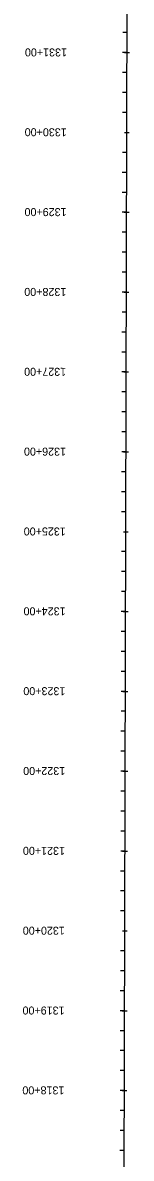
# Model space of a CAD drawing. Extents: x 14541681 to 14544384, y 8572153 to 8583558.
# Drawn here: x 14544128 to 14544264, y 8573573 to 8574996 of the extents above; entities that cross this region are included whole.
import ezdxf

# ---------------------------------------------------------------- set-up
doc = ezdxf.new("R2010")
doc.units = 0
for name, color, linetype in [('Alignment', 7, 'Continuous'), ('TextAlignmentLrg', 7, 'Continuous'), ('TextAlignmentSml', 7, 'Continuous')]:
    doc.layers.add(name, color=color, linetype=linetype)

msp = doc.modelspace()

# ---------------------------------------------------------------- linework, layer by layer
at = {"layer": 'Alignment'}
msp.add_line((14544251.8, 8572158.2), (14544263.9, 8577116.3), dxfattribs=at)
at = {"layer": 'TextAlignmentLrg'}
for p, q in [((14544258.7, 8574958.2), (14544253.2, 8574958.2)), ((14544255.4, 8574858.2), (14544261.5, 8574858.2)), ((14544258.2, 8574758.2), (14544252.7, 8574758.2)), ((14544257.9, 8574658.2), (14544252.5, 8574658.2)), ((14544257.7, 8574558.2), (14544252.2, 8574558.2)), ((14544257.4, 8574458.2), (14544252, 8574458.2)), ((14544254.1, 8574358.2), (14544260.3, 8574358.2)), ((14544257, 8574258.2), (14544251.5, 8574258.2)), ((14544256.7, 8574158.2), (14544251.2, 8574158.2)), ((14544256.5, 8574058.2), (14544251, 8574058.2)), ((14544256.2, 8573958.2), (14544250.8, 8573958.2)), ((14544252.9, 8573858.2), (14544259, 8573858.2)), ((14544255.7, 8573758.2), (14544250.3, 8573758.2)), ((14544255.5, 8573658.2), (14544250, 8573658.2))]:
    msp.add_line(p, q, dxfattribs=at)
at = {"layer": 'TextAlignmentSml'}
for p, q in [((14544258.7, 8574983.2), (14544253.3, 8574983.2)), ((14544255.6, 8574958.2), (14544261.7, 8574958.2)), ((14544258.6, 8574933.2), (14544253.1, 8574933.2)), ((14544258.5, 8574908.2), (14544253.1, 8574908.2)), ((14544258.5, 8574883.2), (14544253, 8574883.2)), ((14544255.4, 8574858.2), (14544261.5, 8574858.2)), ((14544258.4, 8574833.2), (14544252.9, 8574833.2)), ((14544258.3, 8574808.2), (14544252.8, 8574808.2)), ((14544258.2, 8574783.2), (14544252.8, 8574783.2)), ((14544255.1, 8574758.2), (14544261.2, 8574758.2)), ((14544258.1, 8574733.2), (14544252.6, 8574733.2)), ((14544258, 8574708.2), (14544252.6, 8574708.2)), ((14544258, 8574683.2), (14544252.5, 8574683.2)), ((14544254.9, 8574658.2), (14544261, 8574658.2)), ((14544257.9, 8574633.2), (14544252.4, 8574633.2)), ((14544257.8, 8574608.2), (14544252.3, 8574608.2)), ((14544257.7, 8574583.2), (14544252.3, 8574583.2)), ((14544254.6, 8574558.2), (14544260.7, 8574558.2)), ((14544257.6, 8574533.2), (14544252.2, 8574533.2)), ((14544257.6, 8574508.2), (14544252.1, 8574508.2)), ((14544257.5, 8574483.2), (14544252, 8574483.2)), ((14544254.4, 8574458.2), (14544260.5, 8574458.2)), ((14544257.4, 8574433.2), (14544251.9, 8574433.2)), ((14544257.3, 8574408.2), (14544251.9, 8574408.2)), ((14544257.3, 8574383.2), (14544251.8, 8574383.2)), ((14544254.1, 8574358.2), (14544260.3, 8574358.2)), ((14544257.1, 8574333.2), (14544251.7, 8574333.2)), ((14544257.1, 8574308.2), (14544251.6, 8574308.2)), ((14544257, 8574283.2), (14544251.6, 8574283.2)), ((14544253.9, 8574258.2), (14544260, 8574258.2)), ((14544256.9, 8574233.2), (14544251.4, 8574233.2)), ((14544256.8, 8574208.2), (14544251.4, 8574208.2)), ((14544256.8, 8574183.2), (14544251.3, 8574183.2)), ((14544253.6, 8574158.2), (14544259.8, 8574158.2)), ((14544256.6, 8574133.2), (14544251.2, 8574133.2)), ((14544256.6, 8574108.2), (14544251.1, 8574108.2)), ((14544256.5, 8574083.2), (14544251.1, 8574083.2)), ((14544253.4, 8574058.2), (14544259.5, 8574058.2)), ((14544256.4, 8574033.2), (14544250.9, 8574033.2)), ((14544256.3, 8574008.2), (14544250.9, 8574008.2)), ((14544256.3, 8573983.2), (14544250.8, 8573983.2)), ((14544253.2, 8573958.2), (14544259.3, 8573958.2)), ((14544256.2, 8573933.2), (14544250.7, 8573933.2)), ((14544256.1, 8573908.2), (14544250.6, 8573908.2)), ((14544256, 8573883.2), (14544250.6, 8573883.2)), ((14544252.9, 8573858.2), (14544259, 8573858.2)), ((14544255.9, 8573833.2), (14544250.5, 8573833.2)), ((14544255.9, 8573808.2), (14544250.4, 8573808.2)), ((14544255.8, 8573783.2), (14544250.3, 8573783.2)), ((14544252.7, 8573758.2), (14544258.8, 8573758.2)), ((14544255.7, 8573733.2), (14544250.2, 8573733.2)), ((14544255.6, 8573708.2), (14544250.2, 8573708.2)), ((14544255.6, 8573683.2), (14544250.1, 8573683.2)), ((14544252.4, 8573658.2), (14544258.5, 8573658.2)), ((14544255.4, 8573633.2), (14544250, 8573633.2)), ((14544255.4, 8573608.2), (14544249.9, 8573608.2)), ((14544255.3, 8573583.2), (14544249.8, 8573583.2))]:
    msp.add_line(p, q, dxfattribs=at)

# ---------------------------------------------------------------- texts
at = {"layer": 'TextAlignmentLrg'}
for s, p in [('1330+00', (14544183.4, 8574863.4)), ('1325+00', (14544182.2, 8574363.4)), ('1320+00', (14544181, 8573863.4))]:
    msp.add_text(s, height=10.02, rotation=179.8604, dxfattribs=at).set_placement(p)
at = {"layer": 'TextAlignmentSml'}
for s, p in [('1331+00', (14544183.7, 8574963.4)), ('1330+00', (14544183.4, 8574863.4)), ('1329+00', (14544183.2, 8574763.4)), ('1328+00', (14544182.9, 8574663.4)), ('1327+00', (14544182.7, 8574563.4)), ('1326+00', (14544182.5, 8574463.4)), ('1325+00', (14544182.2, 8574363.4)), ('1324+00', (14544182, 8574263.4)), ('1323+00', (14544181.7, 8574163.4)), ('1322+00', (14544181.5, 8574063.4)), ('1321+00', (14544181.2, 8573963.4)), ('1320+00', (14544181, 8573863.4)), ('1319+00', (14544180.7, 8573763.4)), ('1318+00', (14544180.5, 8573663.4))]:
    msp.add_text(s, height=10.02, rotation=179.8604, dxfattribs=at).set_placement(p)

doc.saveas('drawing.dxf')
